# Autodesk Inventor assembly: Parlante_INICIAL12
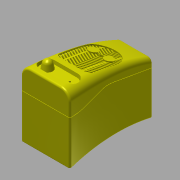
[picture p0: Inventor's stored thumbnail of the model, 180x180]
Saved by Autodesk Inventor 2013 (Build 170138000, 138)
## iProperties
Created: 2013-03
Part Number: Parlante_INICIAL12
Document SubType Name: Assembly
Designer: julian.chica
Author: julian.chica
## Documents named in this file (4)
- C:\Autodesk Learning\MULTICUERPO\2011 Medical Devices\Parlante_INICIAL12.iam
- C:\Autodesk Learning\MULTICUERPO\2011 Medical Devices\frontal.ipt
- C:\Autodesk Learning\MULTICUERPO\2011 Medical Devices\trasero.ipt
- C:\Autodesk Learning\MULTICUERPO\2011 Medical Devices\Perilla.ipt
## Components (3 placed, 3 different names)
1. frontal:1
2. trasero:1
3. Perilla:1
